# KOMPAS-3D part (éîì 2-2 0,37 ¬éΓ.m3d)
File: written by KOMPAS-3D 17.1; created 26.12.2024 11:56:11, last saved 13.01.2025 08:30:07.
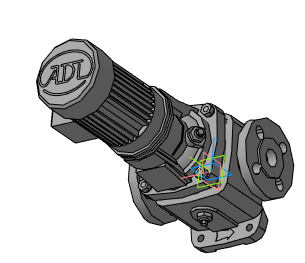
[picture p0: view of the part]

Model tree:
1. Операция без истории:3  (labels: ВМН 2-2 0,37 кВт)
